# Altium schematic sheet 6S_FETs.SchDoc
size 431 x 279 mm; Date: Not shown in title block; ApprovedBy: Not shown in title block; CheckedBy: Not shown in title block; Author: Not shown in title block; CompanyName: Not shown in title block; Address1: Not shown in title block; Address2: Not shown in title block; Address3: Not shown in title block; Address4: Not shown in title block; DocumentNumber: 1; Revision: 1.00; SheetNumber: 1; SheetTotal: 1; PageSetup: Record=PageOptions¦CenterHorizontal=True¦CenterVertical=True¦PrintScale=0.64¦XCorrection=1.00¦YCorrection=1.00¦PrintKind=0¦BorderSize=5000000¦LeftOffset=0¦BottomOffset=0¦Orientation=2¦PaperLength=1000¦PaperWidth=1000¦Scale=100¦PaperSource=15¦PrintQuality=600¦MediaType=1¦DitherType=10¦PrintScaleMode=1¦PaperKind=Letter
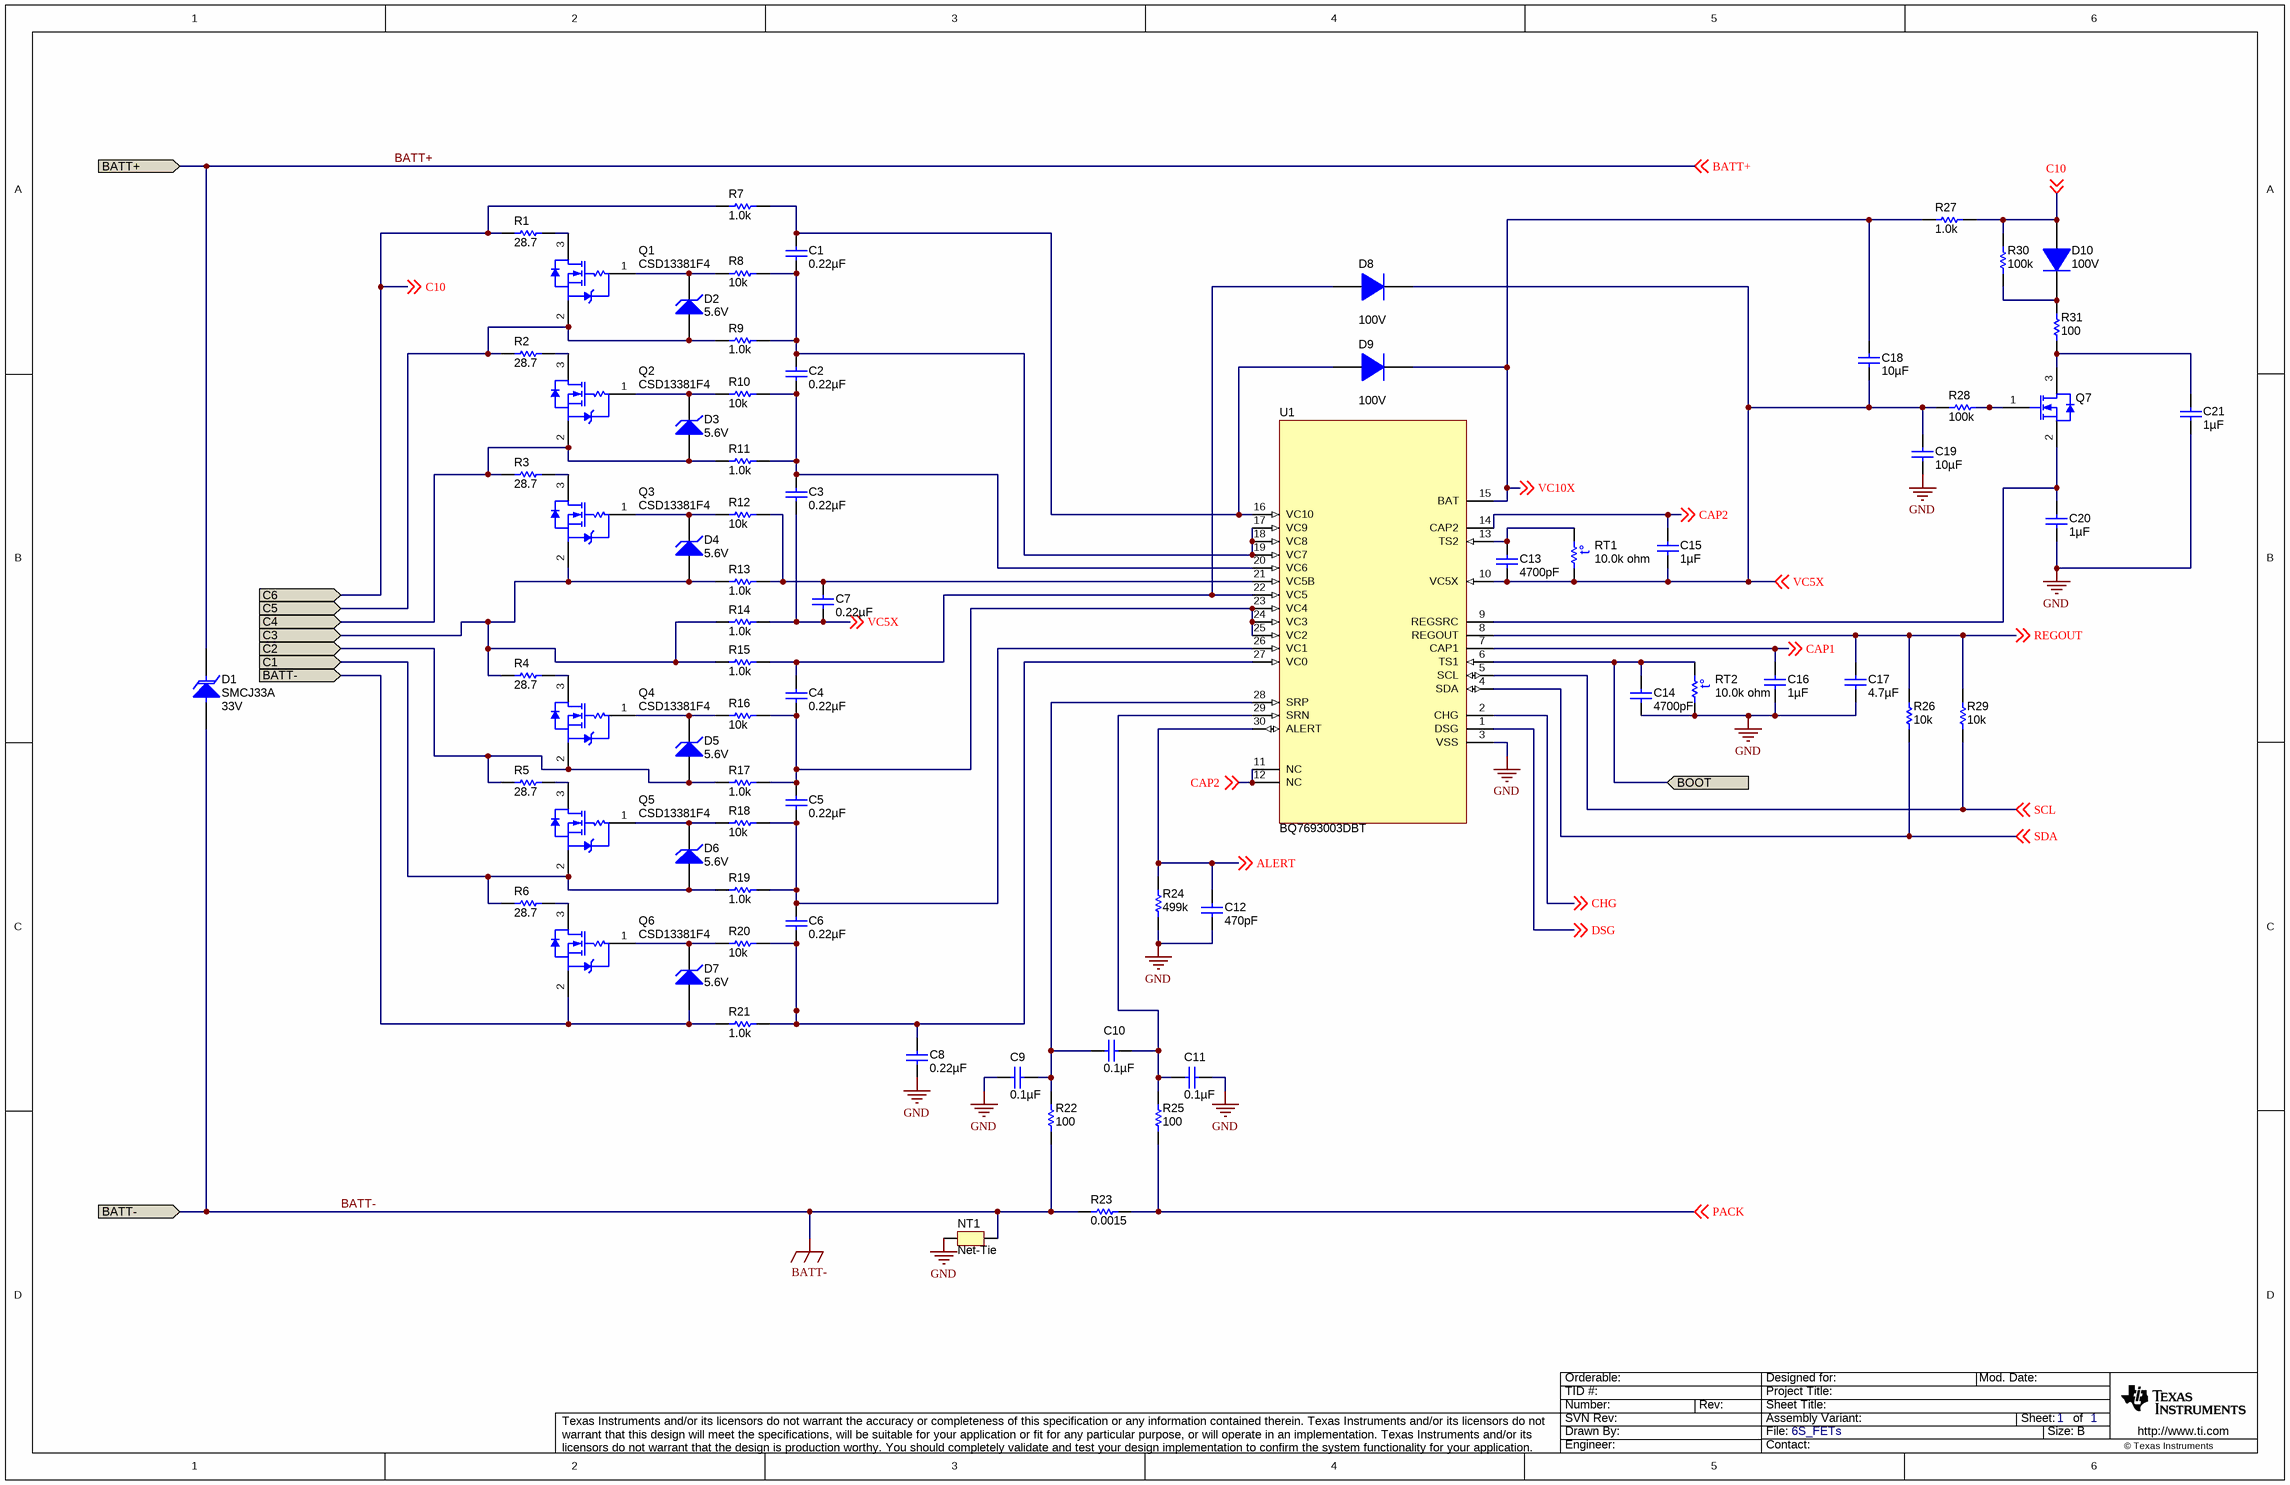
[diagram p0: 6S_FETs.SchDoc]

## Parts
C1  ValueDisplayed: 0.22µF  [0603_095]  (hidden comment: 885012206048)
C2  ValueDisplayed: 0.22µF  [0603_095]  (hidden comment: 885012206048)
C3  ValueDisplayed: 0.22µF  [0603_095]  (hidden comment: 885012206048)
C4  ValueDisplayed: 0.22µF  [0603_095]  (hidden comment: 885012206048)
C5  ValueDisplayed: 0.22µF  [0603_095]  (hidden comment: 885012206048)
C6  ValueDisplayed: 0.22µF  [0603_095]  (hidden comment: 885012206048)
C7  ValueDisplayed: 0.22µF  [0603_095]  (hidden comment: 885012206048)
C8  ValueDisplayed: 0.22µF  [0603_095]  (hidden comment: 885012206048)
C9  ValueDisplayed: 0.1µF  [0603_095]  (hidden comment: 885012206095)
C10  ValueDisplayed: 0.1µF  [0603_095]  (hidden comment: 885012206095)
C11  ValueDisplayed: 0.1µF  [0603_095]  (hidden comment: 885012206095)
C12  ValueDisplayed: 470pF  [0603_095]  (hidden comment: 885012206081)
C13  ValueDisplayed: 4700pF  [0603_095]  (hidden comment: 885012206087)
C14  ValueDisplayed: 4700pF  [0603_095]  (hidden comment: 885012206087)
C15  ValueDisplayed: 1µF  [0603_095]  (hidden comment: 885012206052)
C16  ValueDisplayed: 1µF  [0603_095]  (hidden comment: 885012206052)
C17  ValueDisplayed: 4.7µF  [0805_145]  (hidden comment: 885012207025)
C18  ValueDisplayed: 10µF  [1210]  (hidden comment: GRM32ER7YA106KA12L)
C19  ValueDisplayed: 10µF  [1210]  (hidden comment: GRM32ER7YA106KA12L)
C20  ValueDisplayed: 1µF  [0805]  (hidden comment: GRM21BR71H105KA12L)
C21  ValueDisplayed: 1µF  [0805_HV]  (hidden comment: GRM21BR71H105KA12L)
D1  SMCJ33A  value 33V  [SMC]
D2  value 5.6V  [sod-323]  (hidden comment: MMSZ5232BS-7-F)
D3  value 5.6V  [sod-323]  (hidden comment: MMSZ5232BS-7-F)
D4  value 5.6V  [sod-323]  (hidden comment: MMSZ5232BS-7-F)
D5  value 5.6V  [sod-323]  (hidden comment: MMSZ5232BS-7-F)
D6  value 5.6V  [sod-323]  (hidden comment: MMSZ5232BS-7-F)
D7  value 5.6V  [sod-323]  (hidden comment: MMSZ5232BS-7-F)
D8  value 100V  [SOD-123]  (hidden comment: 1N4148W-7-F)
D9  value 100V  [SOD-123]  (hidden comment: 1N4148W-7-F)
D10  value 100V  [SOD-123]  (hidden comment: 1N4148W-7-F)
NT1  Net-Tie  [Net-Tie_10mil]  (net tie, no BOM)
Q1  CSD13381F4  [YJC0003A]
Q2  CSD13381F4  [YJC0003A]
Q3  CSD13381F4  [YJC0003A]
Q4  CSD13381F4  [YJC0003A]
Q5  CSD13381F4  [YJC0003A]
Q6  CSD13381F4  [YJC0003A]
Q7  2N7002ET1G  [SOT-23]  (value not drawn)
R1  ValueDisplayed: 28.7  [2010]  (hidden comment: CRCW201028R7FKEF)
R2  ValueDisplayed: 28.7  [2010]  (hidden comment: CRCW201028R7FKEF)
R3  ValueDisplayed: 28.7  [2010]  (hidden comment: CRCW201028R7FKEF)
R4  ValueDisplayed: 28.7  [2010]  (hidden comment: CRCW201028R7FKEF)
R5  ValueDisplayed: 28.7  [2010]  (hidden comment: CRCW201028R7FKEF)
R6  ValueDisplayed: 28.7  [2010]  (hidden comment: CRCW201028R7FKEF)
R7  ValueDisplayed: 1.0k  [0603]  (hidden comment: CRCW06031K00JNEA)
R8  ValueDisplayed: 10k  [0603]  (hidden comment: CRCW060310K0JNEA)
R9  ValueDisplayed: 1.0k  [0603]  (hidden comment: CRCW06031K00JNEA)
R10  ValueDisplayed: 10k  [0603]  (hidden comment: CRCW060310K0JNEA)
R11  ValueDisplayed: 1.0k  [0603]  (hidden comment: CRCW06031K00JNEA)
R12  ValueDisplayed: 10k  [0603]  (hidden comment: CRCW060310K0JNEA)
R13  ValueDisplayed: 1.0k  [0603]  (hidden comment: CRCW06031K00JNEA)
R14  ValueDisplayed: 1.0k  [0603]  (hidden comment: CRCW06031K00JNEA)
R15  ValueDisplayed: 1.0k  [0603]  (hidden comment: CRCW06031K00JNEA)
R16  ValueDisplayed: 10k  [0603]  (hidden comment: CRCW060310K0JNEA)
R17  ValueDisplayed: 1.0k  [0603]  (hidden comment: CRCW06031K00JNEA)
R18  ValueDisplayed: 10k  [0603]  (hidden comment: CRCW060310K0JNEA)
R19  ValueDisplayed: 1.0k  [0603]  (hidden comment: CRCW06031K00JNEA)
R20  ValueDisplayed: 10k  [0603]  (hidden comment: CRCW060310K0JNEA)
R21  ValueDisplayed: 1.0k  [0603]  (hidden comment: CRCW06031K00JNEA)
R22  value 100  [0805_HV]  (hidden comment: CRCW0805100RFKEA)
R23  ValueDisplayed: 0.0015  [ULRB22512_085]  (hidden comment: ULRB22512R0015FLFSLT)
R24  ValueDisplayed: 499k  [0603]  (hidden comment: CRCW0603499KFKEA)
R25  value 100  [0805_HV]  (hidden comment: CRCW0805100RFKEA)
R26  ValueDisplayed: 10k  [0603]  (hidden comment: CRCW060310K0JNEA)
R27  ValueDisplayed: 1.0k  [0603]  (hidden comment: CRCW06031K00JNEA)
R28  value 100k  [0805_HV]  (hidden comment: CRCW0805100KFKEA)
R29  ValueDisplayed: 10k  [0603]  (hidden comment: CRCW060310K0JNEA)
R30  value 100k  [0805_HV]  (hidden comment: CRCW0805100KFKEA)
R31  value 100  [0805_HV]  (hidden comment: CRCW0805100RFKEA)
RT1  value 10.0k ohm  [Thermistor_103AT-2]  (hidden comment: 103AT-2)
RT2  value 10.0k ohm  [Thermistor_103AT-2]  (hidden comment: 103AT-2)
U1  BQ7693003DBT  [DBT0030A_N]

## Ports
BATT+, BATT-, BOOT, C1, C2, C3, C4, C5, C6

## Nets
BATT-: D1.2(A) D7.2(A) NT1.2 Q6.2(S) R21.1 R22.1 R23.1 ; port BATT-
GND: C8.2 C9.2 C11.1 C12.2 C14.2 C16.2 C17.2 C19.2 C20.2 C21.2 NT1.1 R24.1 RT2.1 U1.3(VSS)
ALERT: C12.1 R24.2 U1.30(ALERT) ; off-sheet ALERT
BATT+: D1.1(K) ; off-sheet BATT+, port BATT+
BOOT: C14.1 RT2.2 U1.6(TS1) ; port BOOT
C1: D6.2(A) Q5.2(S) R6.1 R19.1 ; port C1
C2: D5.2(A) Q4.2(S) R5.1 R17.1 ; port C2
C3: D4.2(A) Q3.2(S) R4.1 R13.1 R14.1 R15.1 ; port C3
C4: D3.2(A) Q2.2(S) R3.1 R11.1 ; port C4
C5: D2.2(A) Q1.2(S) R2.1 R9.1 ; port C5
C10: D10.2(A) R1.1 R7.1 R27.2 R30.1 ; off-sheet C10, port C6
CAP1: C16.1 U1.7(CAP1) ; off-sheet CAP1
CAP2: C15.1 U1.11(NC) U1.12(NC) U1.14(CAP2) ; off-sheet CAP2
CHG: U1.2(CHG) ; off-sheet CHG
DSG: U1.1(DSG) ; off-sheet DSG
PACK: R23.2 R25.1 ; off-sheet PACK
REGOUT: C17.1 R26.2 R29.1 U1.8(REGOUT) ; off-sheet REGOUT
SCL: R29.2 U1.5(SCL) ; off-sheet SCL
SDA: R26.1 U1.4(SDA) ; off-sheet SDA
VC5X: C3.2 C7.2 C13.2 C15.2 C18.2 C19.1 D8.1(K) R14.2 R28.1 RT1.1 U1.10(VC5X) ; off-sheet VC5X
VC10X: C18.1 D9.1(K) R27.1 U1.15(BAT) ; off-sheet VC10X
NetC1_1: C1.1 D9.2(A) R7.2 U1.16(VC10)
NetC1_2: C1.2 C2.1 R8.2 R9.2 U1.17(VC9) U1.18(VC8) U1.19(VC7)
NetC2_2: C2.2 C3.1 R10.2 R11.2 U1.20(VC6)
NetC4_1: C4.1 D8.2(A) R15.2 U1.22(VC5)
NetC4_2: C4.2 C5.1 R16.2 R17.2 U1.23(VC4) U1.24(VC3) U1.25(VC2)
NetC5_2: C5.2 C6.1 R18.2 R19.2 U1.26(VC1)
NetC6_2: C6.2 C8.1 R20.2 R21.2 U1.27(VC0)
NetC7_1: C7.1 R12.2 R13.2 U1.21(VC5B)
NetC9_1: C9.1 C10.2 R22.2 U1.28(SRP)
NetC10_1: C10.1 C11.2 R25.2 U1.29(SRN)
NetC13_1: C13.1 RT1.2 U1.13(TS2)
NetC20_1: C20.1 Q7.2(S) U1.9(REGSRC)
NetC21_1: C21.1 Q7.3(D) R31.2
NetD2_1: D2.1(K) Q1.1(G) R8.1
NetD3_1: D3.1(K) Q2.1(G) R10.1
NetD4_1: D4.1(K) Q3.1(G) R12.1
NetD5_1: D5.1(K) Q4.1(G) R16.1
NetD6_1: D6.1(K) Q5.1(G) R18.1
NetD7_1: D7.1(K) Q6.1(G) R20.1
NetD10_1: D10.1(K) R30.2 R31.1
NetQ1_3: Q1.3(D) R1.2
NetQ2_3: Q2.3(D) R2.2
NetQ3_3: Q3.3(D) R3.2
NetQ4_3: Q4.3(D) R4.2
NetQ5_3: Q5.3(D) R5.2
NetQ6_3: Q6.3(D) R6.2
NetQ7_1: Q7.1(G) R28.2

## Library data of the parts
C1-C8 = 885012206048: CAP, CERM, 0.22 µF, 16 V, +/- 10%, X7R, 0603_095; Manufacturer: Wurth Elektronik; Polarized: N; CompType: Capacitor; Value: 0.22uF; U/M: EA; Cap_F: 0.00000022; Tolerance_%: 10; Value1: Unknown; VDC_V: 16; Value2: 16V; TaMin_C: -55; TaMax_C: 125; Cap_Case: 0603
C9-C11 = 885012206095: CAP, CERM, 0.1 µF, 50 V, +/- 10%, X7R, 0603_095; Manufacturer: Wurth Elektronik; Polarized: N; CompType: Capacitor; Value: 0.1uF; U/M: EA; Cap_F: 0.0000001; Tolerance_%: 10; Value1: Unknown; VDC_V: 50; Value2: 50V; TaMin_C: -55; TaMax_C: 125; Cap_Case: 0603
C12 = 885012206081: CAP, CERM, 470 pF, 50 V, +/- 10%, X7R, 0603_095; Manufacturer: Wurth Elektronik; Polarized: N; CompType: Capacitor; Value: 470pF; U/M: EA; Cap_F: 0.00000000047; Tolerance_%: 10; Value1: Unknown; VDC_V: 50; Value2: 50V; TaMin_C: -55; TaMax_C: 125; Cap_Case: 0603
C13 C14 = 885012206087: CAP, CERM, 4700 pF, 50 V, +/- 10%, X7R, 0603_095; Manufacturer: Wurth Elektronik; Polarized: N; CompType: Capacitor; Value: 4700pF; U/M: EA; Cap_F: 0.0000000047; Tolerance_%: 10; Value1: Unknown; VDC_V: 50; Value2: 50V; TaMin_C: -55; TaMax_C: 125; Cap_Case: 0603
C15 C16 = 885012206052: CAP, CERM, 1 µF, 16 V, +/- 10%, X7R, 0603_095; Manufacturer: Wurth Elektronik; Polarized: N; CompType: Capacitor; Value: 1uF; U/M: EA; Cap_F: 0.000001; Tolerance_%: 10; Value1: Unknown; VDC_V: 16; Value2: 16V; TaMin_C: -55; TaMax_C: 125; Cap_Case: 0603
C17 = 885012207025: CAP, CERM, 4.7 µF, 10 V, +/- 10%, X7R, 0805; Manufacturer: Wurth Elektronik; Polarized: N; CompType: Capacitor; Value: 4.7uF; U/M: EA; Cap_F: 0.0000047; Tolerance_%: 10; Value1: Unknown; Value2: 10V; TaMin_C: -55; TaMax_C: 125; Cap_Case: 0805
C18 C19 = GRM32ER7YA106KA12L: CAP, CERM, 10uF, 35V, +/-10%, X7R, 1210; Manufacturer: MuRata; Polarized: N; CompType: Capacitor; U/M: EA; Cap_F: 0.00001; Tolerance_%: 10; Value1: Unknown; VDC_V: 35; TaMin_C: -55; TaMax_C: 125
C20 = GRM21BR71H105KA12L: CAP, CERM, 1 µF, 50 V, +/- 10%, X7R, 0805; Manufacturer: MuRata; Polarized: N; CompType: Capacitor; Value: 1uF; U/M: EA; Cap_F: 0.000001; Tolerance_%: 10; Value1: Unknown; VDC_V: 50; Value2: 50V; TaMin_C: -55; TaMax_C: 125
C21 = GRM21BR71H105KA12L: CAP, CERM, 1 µF, 50 V, +/- 10%, X7R, 0805; Manufacturer: MuRata; Polarized: N; CompType: Capacitor; Value: 1uF; U/M: EA; Cap_F: 0.000001; Tolerance_%: 10; Value1: Unknown; VDC_V: 50; Value2: 50V; TaMin_C: -55; TaMax_C: 125; Cap_Case: 0805
D1 = SMCJ33A: Diode, TVS, Uni, 33 V, SMC; Manufacturer: Bourns; U/M: EA; Power_W: 5; Vr_V: 33; Value1: 5W; SizeAreaWB_mm2: 83.2686; SizeArea_mm2: 50.5686; SizeX_mm: 8.13; SizeY_mm: 6.22; SizeZ_mm: 2.6; AEC Category: Q101
D2-D7 = MMSZ5232BS-7-F: Diode, Zener, 5.6V, 200mW, SOD-323; Manufacturer: Diodes Inc.; U/M: EA; Power_W: 0.2; Vz_V: 5.6; Value1: 0.2W; RJA_CperW: 350
D8 D9 = 1N4148W-7-F: Diode, Ultrafast, 100V, 0.15A, SOD-123; Manufacturer: Diodes Inc.; U/M: EA; Vf_V: 1.25; Value2: 1.25V; Io_A: 0.15; Vr_V: 100; TJmax_C: 150
D10 = 1N4148W-7-F: Diode, Ultrafast, 100V, 0.15A, SOD-123; Manufacturer: Diodes Inc.; U/M: EA; Vf_V: 1.25; Io_A: 0.15; Vr_V: 100; Value2: 1.25V; TJmax_C: 150
NT1 = Net-Tie: Single point connection between nets.; SymbolCreator: codlsc
Q1-Q6 = CSD13381F4: MOSFET, N/P-CH, 12 V, 2.1 A, 1.0x0.35x0.6mm; Manufacturer: Texas Instruments; Alternate Manufacturer: None; SymbolCreator: a0411947; U/M: EA; ChType: N; Value: 12V; VdsMax_V: 12; Value1: 0.14 ohm; Rdson45_ohm: 0.14; Value2: 1.06 nC; QgTyp_nC: 1.06; Vgs_V: 8; IdsMax_A: 2.1
Q7 = 2N7002ET1G: MOSFET, N-CH, 60 V, 0.26 A, SOT-23; Manufacturer: ON Semiconductor; Alternate Manufacturer: None; U/M: EA; ChType: N; Value: 60V; VdsMax_V: 60; Value1: 3 ohm; Rdson45_ohm: 3; Value2: 0.81 nC; QgTyp_nC: 0.81; Vgs_V: 20; IdsMax_A: 0.26
R1-R6 = CRCW201028R7FKEF: RES, 28.7, 1%, 0.75 W, 2010; Manufacturer: Vishay-Dale; CompType: Resistor; Value: 28.7; Value_Code: 28R7; Tolerance_%: 1; Power_W: 0.75; Value2: 0.75W; VDC_V: 400; TempCo: 100 ppm/C; EIA_Code: E96; U/M: EA
R7 R9 R11 R13-R15 R17 R19 R21 R27 = CRCW06031K00JNEA: RES, 1.0 k, 5%, 0.1 W, 0603; Manufacturer: Vishay-Dale; CompType: Resistor; Value: 1.0k; Res_ohm: 1000; Value_Code: 1k00; Tolerance_%: 5; Power_W: 0.1; Value2: 0.1W; VDC_V: 75; TempCo: 200 ppm/C; EIA_Code: E24; U/M: EA
R8 R10 R12 R16 R18 R20 R26 R29 = CRCW060310K0JNEA: RES, 10 k, 5%, 0.1 W, 0603; Manufacturer: Vishay-Dale; CompType: Resistor; Value: 10k; Res_ohm: 10000; Value_Code: 10k0; Tolerance_%: 5; Power_W: 0.1; Value2: 0.1W; VDC_V: 75; TempCo: 200 ppm/C; EIA_Code: E24; U/M: EA
R22 R25 R31 = CRCW0805100RFKEA: RES, 100 ohm, 1%, 0.125W, 0805; Manufacturer: Vishay-Dale; CompType: Resistor; Value_Code: 100R; Tolerance_%: 1; Power_W: 0.125; VDC_V: 150; TempCo: 100 ppm/C; EIA_Code: E96; U/M: EA
R23 = ULRB22512R0015FLFSLT: RES, 0.0015, 1%, 2 W, AEC-Q200 Grade 0, 2512; Manufacturer: TT Electronics/IRC; CompType: Resistor; Value: 0.0015; Value_Code: 1L500; Tolerance_%: 1; Power_W: 2; Value2: 2W; TempCo: 50 ppm/C; U/M: EA; AEC Category: Q200; AEC Qualified: Y; AEC Grade: 0
R24 = CRCW0603499KFKEA: RES, 499 k, 1%, 0.1 W, 0603; Manufacturer: Vishay-Dale; CompType: Resistor; Value: 499k; Res_ohm: 499000; Tolerance_%: 1; Power_W: 0.1; Value2: 0.1W; VDC_V: 75; TempCo: 100 ppm/C; EIA_Code: E96; U/M: EA
R28 R30 = CRCW0805100KFKEA: RES, 100k ohm, 1%, 0.125W, 0805; Manufacturer: Vishay-Dale; CompType: Resistor; Res_ohm: 100000; Tolerance_%: 1; Power_W: 0.125; VDC_V: 150; TempCo: 100 ppm/C; EIA_Code: E96; U/M: EA
RT1 RT2 = 103at-2: Thermistor NTC, 10.0k ohm, 1%, Disc, 5x8.4 mm; Manufacturer: SEMITEC Corporation; Tolerance_%: 1; Power_W: 0.01; TaMin_C: -50; TaMax_C: 110; U/M: EA
U1 = BQ7693003DBT: Battery Monitor for Lithium-Ion and Phosphate Battery Packs, DBT0030A; Manufacturer: Texas Instruments; SymbolCreator: a0799628; CompType: IC; U/M: EA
